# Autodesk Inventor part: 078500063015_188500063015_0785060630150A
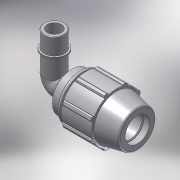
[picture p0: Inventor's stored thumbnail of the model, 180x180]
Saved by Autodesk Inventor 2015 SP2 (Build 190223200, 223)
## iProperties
Created: 2017-02
Part Number: 078500063015_188500063015_0785060630150A
Material: PVC-Piping
Description: PLASSON 90° ELBOW MALE ADAPTOR 63-1.1/2"
Document SubType Name: Modeling
Designer: KIM
Mass: 92.6774 g
Surface Area: 199.44 cm^2
Volume: 66.1981 cm^3
Density: 1.4 g/cm^3
Appearance: Smooth - White
Author: KIM
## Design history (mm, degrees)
derived "07850.ipt"
feature "Solid1::07850.ipt"
tag "TaggingFeature1"
body "Solid1"
other parameters: "d2" = 63, "d4" = 14, "d5" = 42, "d7" = 113, "d9" = 24, "d11" = 5.6, "d13" = 120 deg, "d14" = 81.9, "d15" = 12 deg, "d16" = 98.31, "d18" = 3.15, "d19" = 35 deg, "d20" = 17.5 deg, "d21" = 105.09, "d23" = 0, "d25" = 360 deg, "d27" = 2.26, "d33" = 1.26, "d42" = 62.16, "d43" = 3.39, "d46" = 1.89, "d51" = 168, "d68" = 5.6, "d72" = 76, "d73" = 47.803, "d74" = 22, "d75" = 54.97345, "d76" = 33.4621, "d77" = 24.2, "d79" = 19.1212, "d80" = 1.43409, "d83" = 0, "d84" = 0, "d91" = 84.75, "d94" = 47.803, "d95" = 33.4621, "d96" = 16.8, "d97" = 50 deg, "d_" = 63, "E_" = 113, "A_" = 168, "l_2" = 22, "A_1" = 76, "R_" = 47.803
